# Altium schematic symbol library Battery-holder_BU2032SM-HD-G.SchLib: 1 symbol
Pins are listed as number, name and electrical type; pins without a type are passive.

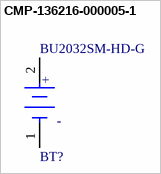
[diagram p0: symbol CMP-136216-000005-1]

## CMP-136216-000005-1
designator BT?, comment BU2032SM-HD-G
BATTERY HOLDER COIN 20MM SMD; Number of Cells: 1
footprint FP-BU2032SM-HD-G-MFG
pins: 1 C, 2 A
